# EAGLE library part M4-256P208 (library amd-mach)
AMD MACH SERIES
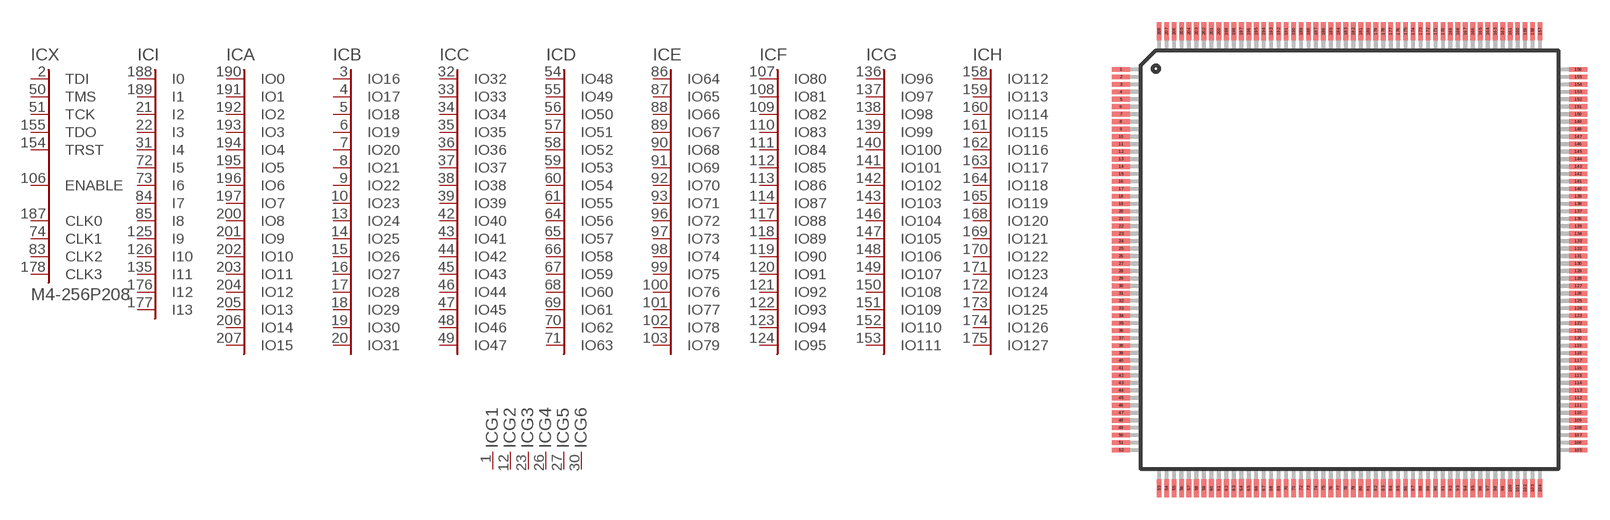
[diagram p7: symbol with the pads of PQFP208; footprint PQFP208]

Designator prefix IC; gates X=M4-256-C A=IO15 B=IO31 C=IO47 D=IO63 E=IO79 F=IO95 G=IO111 H=IO127 I=M4-I13 G1=GND G2=GND G3=GND G4=GND G5=GND G6=GND G7=GND G8=GND G9=GND G10=GND G11=GND G12=GND G13=GND G14=GND G15=GND G16=GND G17=GND G18=GND G19=GND G20=GND G21=GND G22=GND V1=VCC V2=VCC V3=VCC V4=VCC V5=VCC V6=VCC V7=VCC V8=VCC V9=VCC V10=VCC V11=VCC V12=VCC V13=VCC V14=VCC V15=VCC V16=VCC V17=VCC V18=VCC V19=VCC V20=VCC V21=VCC V22=VCC G23=GND G24=GND G25=GND G26=GND G27=GND G28=GND G29=GND G30=GND G31=GND G32=GND V23=VCC V24=VCC

## M4-256P208 (OC_FARNELL: unknown; OC_NEWARK: unknown)  [PQFP208]
1  G1:GND  pwr
2  X:TDI  in
3  B:IO16
4  B:IO17
5  B:IO18
6  B:IO19
7  B:IO20
8  B:IO21
9  B:IO22
10  B:IO23
11  V1:VCC  pwr
12  G2:GND  pwr
13  B:IO24
14  B:IO25
15  B:IO26
16  B:IO27
17  B:IO28
18  B:IO29
19  B:IO30
20  B:IO31
21  I:I2  in
22  I:I3  in
23  G3:GND  pwr
24  V2:VCC  pwr
25  V3:VCC  pwr
26  G4:GND  pwr
27  G5:GND  pwr
28  V4:VCC  pwr
29  V5:VCC  pwr
30  G6:GND  pwr
31  I:I4  in
32  C:IO32
33  C:IO33
34  C:IO34
35  C:IO35
36  C:IO36
37  C:IO37
38  C:IO38
39  C:IO39
40  G7:GND  pwr
41  V6:VCC  pwr
42  C:IO40
43  C:IO41
44  C:IO42
45  C:IO43
46  C:IO44
47  C:IO45
48  C:IO46
49  C:IO47
50  X:TMS  in
51  X:TCK  in
52  G8:GND  pwr
53  G9:GND  pwr
54  D:IO48
55  D:IO49
56  D:IO50
57  D:IO51
58  D:IO52
59  D:IO53
60  D:IO54
61  D:IO55
62  G10:GND  pwr
63  V7:VCC  pwr
64  D:IO56
65  D:IO57
66  D:IO58
67  D:IO59
68  D:IO60
69  D:IO61
70  D:IO62
71  D:IO63
72  I:I5  in
73  I:I6  in
74  X:CLK1  in
75  V8:VCC  pwr
76  G11:GND  pwr
77  G12:GND  pwr
78  V9:VCC  pwr
79  V10:VCC  pwr
80  G13:GND  pwr
81  G14:GND  pwr
82  V11:VCC  pwr
83  X:CLK2  in
84  I:I7  in
85  I:I8  in
86  E:IO64
87  E:IO65
88  E:IO66
89  E:IO67
90  E:IO68
91  E:IO69
92  E:IO70
93  E:IO71
94  V12:VCC  pwr
95  G15:GND  pwr
96  E:IO72
97  E:IO73
98  E:IO74
99  E:IO75
100  E:IO76
101  E:IO77
102  E:IO78
103  E:IO79
104  G16:GND  pwr
105  G17:GND  pwr
106  X:ENABLE  in
107  F:IO80
108  F:IO81
109  F:IO82
110  F:IO83
111  F:IO84
112  F:IO85
113  F:IO86
114  F:IO87
115  V13:VCC  pwr
116  G18:GND  pwr
117  F:IO88
118  F:IO89
119  F:IO90
120  F:IO91
121  F:IO92
122  F:IO93
123  F:IO94
124  F:IO95
125  I:I9  in
126  I:I10  in
127  G19:GND  pwr
128  V14:VCC  pwr
129  V15:VCC  pwr
130  G20:GND  pwr
131  G21:GND  pwr
132  V16:VCC  pwr
133  V17:VCC  pwr
134  G22:GND  pwr
135  I:I11  in
136  G:IO96
137  G:IO97
138  G:IO98
139  G:IO99
140  G:IO100
141  G:IO101
142  G:IO102
143  G:IO103
144  G23:GND  pwr
145  V18:VCC  pwr
146  G:IO104
147  G:IO105
148  G:IO106
149  G:IO107
150  G:IO108
151  G:IO109
152  G:IO110
153  G:IO111
154  X:TRST  in
155  X:TDO  in
156  G24:GND  pwr
157  G25:GND  pwr
158  H:IO112
159  H:IO113
160  H:IO114
161  H:IO115
162  H:IO116
163  H:IO117
164  H:IO118
165  H:IO119
166  G26:GND  pwr
167  V19:VCC  pwr
168  H:IO120
169  H:IO121
170  H:IO122
171  H:IO123
172  H:IO124
173  H:IO125
174  H:IO126
175  H:IO127
176  I:I12  in
177  I:I13  in
178  X:CLK3  in
179  V20:VCC  pwr
180  G27:GND  pwr
181  G28:GND  pwr
182  V21:VCC  pwr
183  V22:VCC  pwr
184  G29:GND  pwr
185  G30:GND  pwr
186  V23:VCC  pwr
187  X:CLK0  in
188  I:I0  in
189  I:I1  in
190  A:IO0
191  A:IO1
192  A:IO2
193  A:IO3
194  A:IO4
195  A:IO5
196  A:IO6
197  A:IO7
198  V24:VCC  pwr
199  G31:GND  pwr
200  A:IO8
201  A:IO9
202  A:IO10
203  A:IO11
204  A:IO12
205  A:IO13
206  A:IO14
207  A:IO15
208  G32:GND  pwr

## Footprint PQFP208 (pad centres in mm)
PLASTIC QUAD FLAT PACK
smd 1.2 x 0.32: 1 -15.3,12.75; 2 -15.3,12.25; 3 -15.3,11.75; 4 -15.3,11.25; 5 -15.3,10.75; 6 -15.3,10.25; 7 -15.3,9.75; 8 -15.3,9.25; 9 -15.3,8.75; 10 -15.3,8.25; 11 -15.3,7.75; 12 -15.3,7.25; 13 -15.3,6.75; 14 -15.3,6.25; 15 -15.3,5.75; 16 -15.3,5.25; 17 -15.3,4.75; 18 -15.3,4.25; 19 -15.3,3.75; 20 -15.3,3.25; 21 -15.3,2.75; 22 -15.3,2.25; 23 -15.3,1.75; 24 -15.3,1.25; 25 -15.3,0.75; 26 -15.3,0.25; 27 -15.3,-0.25; 28 -15.3,-0.75; 29 -15.3,-1.25; 30 -15.3,-1.75; 31 -15.3,-2.25; 32 -15.3,-2.75; 33 -15.3,-3.25; 34 -15.3,-3.75; 35 -15.3,-4.25; 36 -15.3,-4.75; 37 -15.3,-5.25; 38 -15.3,-5.75; 39 -15.3,-6.25; 40 -15.3,-6.75; 41 -15.3,-7.25; 42 -15.3,-7.75; 43 -15.3,-8.25; 44 -15.3,-8.75; 45 -15.3,-9.25; 46 -15.3,-9.75; 47 -15.3,-10.25; 48 -15.3,-10.75; 49 -15.3,-11.25; 50 -15.3,-11.75; 51 -15.3,-12.25; 52 -15.3,-12.75; 105 15.3,-12.75; 106 15.3,-12.25; 107 15.3,-11.75; 108 15.3,-11.25; 109 15.3,-10.75; 110 15.3,-10.25; 111 15.3,-9.75; 112 15.3,-9.25; 113 15.3,-8.75; 114 15.3,-8.25; 115 15.3,-7.75; 116 15.3,-7.25; 117 15.3,-6.75; 118 15.3,-6.25; 119 15.3,-5.75; 120 15.3,-5.25; 121 15.3,-4.75; 122 15.3,-4.25; 123 15.3,-3.75; 124 15.3,-3.25; 125 15.3,-2.75; 126 15.3,-2.25; 127 15.3,-1.75; 128 15.3,-1.25; 129 15.3,-0.75; 130 15.3,-0.25; 131 15.3,0.25; 132 15.3,0.75; 133 15.3,1.25; 134 15.3,1.75; 135 15.3,2.25; 136 15.3,2.75; 137 15.3,3.25; 138 15.3,3.75; 139 15.3,4.25; 140 15.3,4.75; 141 15.3,5.25; 142 15.3,5.75; 143 15.3,6.25; 144 15.3,6.75; 145 15.3,7.25; 146 15.3,7.75; 147 15.3,8.25; 148 15.3,8.75; 149 15.3,9.25; 150 15.3,9.75; 151 15.3,10.25; 152 15.3,10.75; 153 15.3,11.25; 154 15.3,11.75; 155 15.3,12.25; 156 15.3,12.75
smd 0.32 x 1.2: 53 -12.75,-15.3; 54 -12.25,-15.3; 55 -11.75,-15.3; 56 -11.25,-15.3; 57 -10.75,-15.3; 58 -10.25,-15.3; 59 -9.75,-15.3; 60 -9.25,-15.3; 61 -8.75,-15.3; 62 -8.25,-15.3; 63 -7.75,-15.3; 64 -7.25,-15.3; 65 -6.75,-15.3; 66 -6.25,-15.3; 67 -5.75,-15.3; 68 -5.25,-15.3; 69 -4.75,-15.3; 70 -4.25,-15.3; 71 -3.75,-15.3; 72 -3.25,-15.3; 73 -2.75,-15.3; 74 -2.25,-15.3; 75 -1.75,-15.3; 76 -1.25,-15.3; 77 -0.75,-15.3; 78 -0.25,-15.3; 79 0.25,-15.3; 80 0.75,-15.3; 81 1.25,-15.3; 82 1.75,-15.3; 83 2.25,-15.3; 84 2.75,-15.3; 85 3.25,-15.3; 86 3.75,-15.3; 87 4.25,-15.3; 88 4.75,-15.3; 89 5.25,-15.3; 90 5.75,-15.3; 91 6.25,-15.3; 92 6.75,-15.3; 93 7.25,-15.3; 94 7.75,-15.3; 95 8.25,-15.3; 96 8.75,-15.3; 97 9.25,-15.3; 98 9.75,-15.3; 99 10.25,-15.3; 100 10.75,-15.3; 101 11.25,-15.3; 102 11.75,-15.3; 103 12.25,-15.3; 104 12.75,-15.3; 157 12.75,15.3; 158 12.25,15.3; 159 11.75,15.3; 160 11.25,15.3; 161 10.75,15.3; 162 10.25,15.3; 163 9.75,15.3; 164 9.25,15.3; 165 8.75,15.3; 166 8.25,15.3; 167 7.75,15.3; 168 7.25,15.3; 169 6.75,15.3; 170 6.25,15.3; 171 5.75,15.3; 172 5.25,15.3; 173 4.75,15.3; 174 4.25,15.3; 175 3.75,15.3; 176 3.25,15.3; 177 2.75,15.3; 178 2.25,15.3; 179 1.75,15.3; 180 1.25,15.3; 181 0.75,15.3; 182 0.25,15.3; 183 -0.25,15.3; 184 -0.75,15.3; 185 -1.25,15.3; 186 -1.75,15.3; 187 -2.25,15.3; 188 -2.75,15.3; 189 -3.25,15.3; 190 -3.75,15.3; 191 -4.25,15.3; 192 -4.75,15.3; 193 -5.25,15.3; 194 -5.75,15.3; 195 -6.25,15.3; 196 -6.75,15.3; 197 -7.25,15.3; 198 -7.75,15.3; 199 -8.25,15.3; 200 -8.75,15.3; 201 -9.25,15.3; 202 -9.75,15.3; 203 -10.25,15.3; 204 -10.75,15.3; 205 -11.25,15.3; 206 -11.75,15.3; 207 -12.25,15.3; 208 -12.75,15.3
